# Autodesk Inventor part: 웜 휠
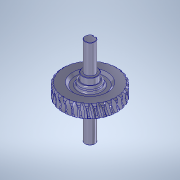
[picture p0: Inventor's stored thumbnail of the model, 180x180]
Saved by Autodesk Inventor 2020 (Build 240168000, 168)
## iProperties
CustomPartVersion: 1
Created: 2013-01
Part Number: 웜 휠
Material: 탄소강
Document SubType Name: Modeling
Designer: 한국산업디자인학원[gmhk.co.kr]
Categories: <?xml version="1.0" encoding="UTF-16"?> <MemberInstance><Categories><FamilyTemplate><FamilyTemplateParameter ValueType="xs:double" Id="1" ObjectReferenceKey="da
Density: 7.87 g/cm^3
Mass: 6989.44 g
Surface Area: 1041.74 cm^2
Volume: 888.112 cm^3
Appearance: _시험-파란색 크롬
Author: 한국산업디자인학원[gmhk.co.kr]
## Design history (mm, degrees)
node "톱니 평면"
sketch "기본 본체 스케치"
  geometry: L1 (0, -14)-(0, 14) reference; L2 (0, 20)-(77.639, 20); L3 (77.639, 20)-(82.5, 15.652); L4 (-10, 0)-(60, 0) reference; L5 (82.5, 15.652)-(82.5, -15.652); L6 (0, -20)-(77.639, -20); L7 (0, 20)-(0, -20); L8 (77.639, -20)-(82.5, -15.652); C1 r 20 at (100, 0)
  constraints: 14 end point, 3 symmetric about line, 2 perpendicular, 2 point on line, 1 centre point, 1 collinear
  dimensions: "d50" = 41.8103 deg angle of L3 L2 (= da_fi); "d87" = 165 diameter of L5 L1 (= da_dae); "d89" = 40 diameter of C1 (= 2 x da_aw - da_da); "d92" = 40 distance of L2.start L6.start (= da_b); "d93" = 100 distance from line of C1.centre L7 (= da_aw)
revolve "기본 본체" stored, may be unused: angle "d35" = 90 deg
revolve "기본 본체2" stored, may be unused: angle "d90" = 90 deg
feature "피치 지름" dims "d78" = 40 (= da_b), "d79" = 0
workplane "Work Plane13"
sketch "톱니 스케치"
  geometry: L1 (10, 5.301)-(10, -5.301) reference; L2 (-32.842, 0)-(-12.948, 0) reference; L3 (-90, 6.896)-(-90, -6.896); L4 (-90, -6.896)-(-71, -6.896); L5 (-71, -6.896)-(-59, -2.529); L6 (-59, -2.529)-(-59, 0); L7 (-59, 2.529)-(-71, 6.896); L8 (-71, 6.896)-(-90, 6.896); L9 (-59, 2.529)-(-59, 0); L10 (-65, 0)-(-65, -4.712)
  constraints: 16 end point, 4 perpendicular, 3 equal length, 2 point on line, 1 midpoint, 1 parallel, 1 vertical
  dimensions: "d38" = 100 distance between parallel lines of L1 L3 (= da_aw); "d39" = 20 deg angle of L7 L8 (= da_alfat); "d40" = 19 distance of L7.end L3.start (= 0.5 x da_df1); "d41" = 25 distance between parallel lines of L3 L10 (= 0.5 x da_d1); "d42" = 4.71239 distance of L10.start L10.end (= 0.3 x da_px)
revolve "톱니" sketch "톱니 스케치" stored, may be unused: angle "d43" = 90 deg
workplane "Work Plane14"
workplane "Work Plane15"
sketch "스케치9"
  geometry: L1 (-74.283, 20)-(-74.054, 20) reference; L2 (-74.054, 20)-(-74.261, 20) reference; L3 (-74.261, 20)-(-75.727, 20) reference; L4 (-77.355, 20)-(-75.727, 20) reference; L5 (-77.355, 20)-(-77.106, 20) reference; L6 (-77.106, 20)-(-76.222, 20) reference; L7 (-76.222, 20)-(-77.633, 20) reference; L8 (-77.045, 20)-(-77.633, 20) reference; L9 (-77.045, 20)-(-76.789, 20) reference; L10 (-76.789, 20)-(-74.852, 20) reference; L11 (-74.852, 20)-(-76.145, 20) reference; L12 (-73.369, 20)-(-76.145, 20) reference; L13 (-73.369, 20)-(-73.116, 20) reference; L14 (-73.116, 20)-(-70.211, 20) reference; L15 (-70.211, 20)-(-71.33, 20) reference; L16 (-66.486, 20)-(-71.33, 20) reference; L17 (-66.486, 20)-(-66.247, 20) reference; L18 (-66.247, 20)-(-62.501, 20) reference; L19 (-62.501, 20)-(-63.397, 20) reference; L20 (-56.697, 20)-(-63.397, 20) reference; L21 (-56.697, 20)-(-56.483, 20) reference; L22 (-56.483, 20)-(-52.059, 20) reference; L23 (-52.059, 20)-(-52.693, 20) reference; L24 (-44.431, 20)-(-52.693, 20) reference; L25 (-44.431, 20)-(-44.25, 20) reference; L26 (-44.25, 20)-(-39.342, 20) reference; L27 (-39.342, 20)-(-39.687, 20) reference; L28 (-30.222, 20)-(-39.687, 20) reference; L29 (-30.222, 20)-(-30.084, 20) reference; L30 (-30.084, 20)-(-24.906, 20) reference; L31 (-24.906, 20)-(-24.945, 20) reference; L32 (-14.693, 20)-(-24.945, 20) reference; L33 (-14.693, 20)-(-14.602, 20) reference; L34 (-14.602, 20)-(-9.381, 20) reference; L35 (-9.381, 20)-(-9.114, 20) reference; L36 (1.479, 20)-(-9.114, 20) reference; L37 (1.479, 20)-(1.517, 20) reference; L38 (1.517, 20)-(6.554, 20) reference; L39 (6.554, 20)-(7.116, 20) reference; L40 (17.586, 20)-(7.116, 20) reference; L41 (17.586, 20)-(17.571, 20) reference; L42 (17.571, 20)-(22.202, 20) reference; L43 (22.202, 20)-(23.034, 20) reference; L44 (32.924, 20)-(23.034, 20) reference; L45 (32.924, 20)-(32.856, 20) reference; L46 (32.856, 20)-(36.88, 20) reference; L47 (36.88, 20)-(37.946, 20) reference; L48 (46.823, 20)-(37.946, 20) reference; L49 (46.823, 20)-(46.705, 20) reference; L50 (46.705, 20)-(49.946, 20) reference; L51 (49.946, 20)-(51.2, 20) reference; L52 (58.676, 20)-(51.2, 20) reference; L53 (58.676, 20)-(58.514, 20) reference; L54 (58.514, 20)-(60.83, 20) reference; L55 (60.83, 20)-(62.216, 20) reference; L56 (67.965, 20)-(62.216, 20) reference; L57 (67.965, 20)-(67.764, 20) reference; L58 (67.764, 20)-(69.055, 20) reference; L59 (69.055, 20)-(70.512, 20) reference; L60 (74.283, 20)-(70.512, 20) reference; L61 (74.283, 20)-(74.054, 20) reference; L62 (74.054, 20)-(74.261, 20) reference; L63 (74.261, 20)-(75.727, 20) reference; L64 (77.355, 20)-(75.727, 20) reference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
  constraints: 8 end point, 3 point on line, 2 perpendicular, 1 parallel
  dimensions: "d94" = 90 diameter of L122.end L121; "d95" = 135 deg angle of L123 L122; "d96" = 13 distance from line of L121.start L122
revolve "회전6" sketch "스케치9" stored, may be unused: angle "d97" = 90 deg
sketch "스케치10"
  geometry: L1 (45, 13)-(-45, 13) reference; L2 (0, 13)-(0, 133); L3 (0, 133)-(-15, 133); L4 (-15, 133)-(-15, 47); L5 (-15, 47)-(-22.5, 47); L6 (-22.5, 47)-(-22.5, 28); L7 (-22.5, 28)-(-30, 28); L8 (-30, 28)-(-30, 13); L9 (30, 47)-(-30, 47) reference; 1 further point
  constraints: 14 end point, 4 parallel, 3 perpendicular, 1 collinear, 1 midpoint, 1 point on line
  dimensions: "d99" = 30 diameter of L4 L2; "d100" = 45 diameter of L6 L2; "d101" = 60 diameter of L8 L2; "d102" = 15 distance between parallel lines of L7 L1; "d103" = 120 distance of L2.start L2.end
revolve "회전7" sketch "스케치10" stored, may be unused: angle "d104" = 90 deg
fillet "모깎기1" dims "d105" = 5
chamfer "모따기1" distance "d106" = 1; stored, may be unused: second distance "d107" = 2, angle "d108" = 45 deg
node "작업 평면16"
sketch "스케치11"
  geometry: L1 (-14, 43)-(14, 43) reference; L2 (4, 43)-(4, 22); L3 (-4, 22)-(-4, 43); A1 r 4 centre (0, 22) between (-4, 22) and (4, 22); 2 further points
  constraints: 4 end point, 2 perpendicular, 2 point on circle, 2 point on line, 2 tangent, 1 centre point, 1 midpoint, 1 vertical alignment
  dimensions: "d109" = 8 distance between parallel lines of L2 L3; "d110" = 25 dimension on A1 L1
extrude "돌출1" cut sketch "스케치11" distance "d111" = 4; taper "d112" = 0 deg
body "Solid1"
pattern_circular "톱니 패턴" dims angle "d46" = 360 deg
mirror "대칭1"
sketch "Sketch8"
  geometry: C1 r 77.639 at (0, 0) reference; C2 r 75 at (0, 0)
  constraints: 1 centre point, 1 coincident
  dimensions: "d77" = 150 diameter of C2 (= da_dw)
body "Srf1"
node "투영된 루프1"
node "참조1"
other parameters: "da_aw" = 100 [user parameter; used in 5 equation terms], "da_fi" = 41.8103 deg [user parameter; used in 1 equation term], "da_b" = 40 [user parameter; used in 2 equation terms], "da_df" = 138 [user parameter], "da_beta" = 1.97396 [user parameter; used in 1 equation term], "da_alfat" = 20 deg [user parameter; used in 1 equation term], "da_df1" = 38 [user parameter; used in 1 equation term], "da_px" = 90 deg [user parameter; used in 1 equation term], "d37" = -1.97396 (computed from da_rightdir, da_beta), "d69" = 0, "d73" = 0, "d75" = 6 deg (computed from da_z), "da_dw" = 150 [user parameter; used in 1 equation term], "da_rightdir" = 0 [user parameter; used in 1 equation term], "d80" = 0, "d81" = 0, "d82" = 0, "d83" = 6 deg (computed from da_z), "d84" = 0, "d85" = 180 deg, "da_dae" = 165 [user parameter; used in 1 equation term]
